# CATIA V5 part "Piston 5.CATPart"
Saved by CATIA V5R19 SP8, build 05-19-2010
Part number: Piston 5
Bounding box of the stored display mesh (mm): x -125 to 25, y -92.024 to 1312.5, z -862.31 to 1464.982
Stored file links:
  C:\Users\ThinkMotion\Desktop\EU_thinkMotion\iao\IAO_MMS_Groupe3\fovide\fovide\Piston 5.CATPart
  C:\Users\ThinkMotion\Desktop\EU_thinkMotion\iao\IAO_MMS_Groupe3\fovide\fovide\fovide.CATProduct
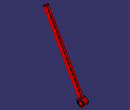
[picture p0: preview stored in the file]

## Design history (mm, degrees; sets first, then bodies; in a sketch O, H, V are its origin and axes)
External parameters (linked from other documents)
  `External.Rayon bielle` = 75 mm
  `External.Diamètre bielle` = 150 mm
Set1
  Plane1: linked copy from another document
  Line1: linked copy from another document
  Point1 "Point.B": linked copy from another document
  Line2: linked copy from another document
Body1 (main body)
  Sketch1 on Plane1, origin (-50, 0, 0), H (0, 1, 0), V (0, 0, 1)
    line L1 (-26.8416, 1428.2699) -> (38.5065, 1465.0751)
    line L2 (38.5065, 1465.0751) -> (1265.3481, -713.1948)
    line L3 (1265.3481, -713.1948) -> (1200, -750)
    line L4 (1200, -750) -> (-26.8416, 1428.2699)
    point P4 (1200, -750)
    reference projected line E1 (-1250, 3600) -> (1200, -750) from Line1
    reference projected point E2 (1200, -750) from Point1
    reference projected line E3 (-1250, 3600) -> (1200, -750) from Line1
    length L1 = 75 {= `External.Rayon bielle`}
    length L4 = 2500
    parallelism: L4 E1, L4 L2, L1 L3, L4 E3
    coincidence: P4 E2
    perpendicularity: L1 L2
  Shaft1: profile Sketch1, axis Sketch1.L4, angle 360
  Sketch2 on Plane1, origin (-50, 0, 0), H (0, 1, 0), V (0, 0, 1)
    circle A1 centre (1200, -750) radius 112.5
    point P1 (1200, -750)
    reference projected point E1 (1200, -750) from Point1
    radius A1 = 112.5 {= `External.Rayon bielle` *1.5}
    coincidence: P1 E1
  Pad1: profile Sketch2, direction (1, 0, 0), length 75 {= `External.Rayon bielle`}, mirrored extent
  Sketch3 on end face of Pad1, origin (25, 1200, -750), H (0, 1, 0), V (0, 0, 1)
    point P1 (0, 0)
    intersected point E1 (0, 0) from Line2
    coincidence: E1 P1
  Hole1: placed by Sketch3, at (25, 1200, -750) direction (-1, 0, 0), diameter 150 {= `External.Diamètre bielle`}, through (limit type 6)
